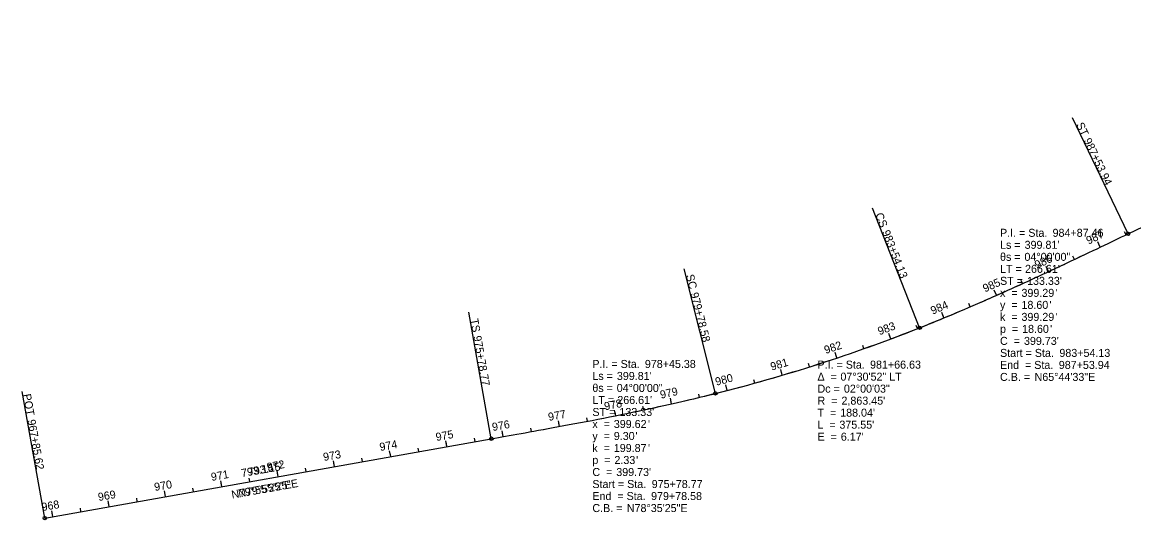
# Model space of a CAD drawing. Extents: x 2192013 to 2197996, y 660216 to 661764.
# Drawn here: x 2192013 to 2193957, y 660216 to 661086 of the extents above; entities that cross this region are included whole.
import ezdxf

# ---------------------------------------------------------------- set-up
doc = ezdxf.new("R2010")
doc.units = 0
for name, color, linetype in [('Default', 7, 'Continuous'), ('GE_X_Alignment', 7, 'Continuous'), ('GE_X_Alignment_1000_Curve_Data', 7, 'Continuous'), ('GE_X_Alignment_1000_Stations', 7, 'Continuous'), ('GE_X_Alignment_100_Curve_Data', 7, 'Continuous'), ('GE_X_Alignment_100_Stations', 7, 'Continuous'), ('GE_X_Alignment_500_Curve_Data', 7, 'Continuous'), ('GE_X_Alignment_500_Stations', 7, 'Continuous'), ('SC_Scratch1', 7, 'Continuous')]:
    doc.layers.add(name, color=color, linetype=linetype)

msp = doc.modelspace()

# ---------------------------------------------------------------- linework, layer by layer
at = {"layer": 'Default'}
for centre in [(2193946.9, 660715.8), (2193946.9, 660715.8), (2193946.9, 660715.8), (2193898.2, 660692.5), (2193807.8, 660649.8), (2193764.7, 660633.7), (2193764.7, 660633.7), (2193764.7, 660633.7), (2193716.8, 660608.3), (2193716.8, 660608.3), (2193625, 660568.8), (2193582.4, 660551.6), (2193582.4, 660551.6), (2193582.4, 660551.6), (2193531.9, 660532.1), (2193403.8, 660494.1), (2193403.8, 660494.1), (2193403.8, 660494.1), (2193437.7, 660498.8), (2193342.3, 660468.7), (2193246, 660441.9), (2193246, 660441.9), (2193246, 660441.9), (2193225.2, 660436.7), (2193225.2, 660436.7), (2193225.2, 660436.7), (2193148.7, 660418.5), (2193029.3, 660397.1), (2193029.3, 660397.1), (2193029.3, 660397.1), (2193050.9, 660397.8), (2192952.7, 660379.1), (2192755.8, 660343.8), (2192755.8, 660343.8), (2192833.4, 660357.6), (2192833.4, 660357.6), (2192833.4, 660357.6), (2192854.3, 660361.3), (2192657.4, 660326.3), (2192558.9, 660308.8), (2192442.9, 660288.2), (2192442.9, 660288.2), (2192442.9, 660288.2), (2192442.9, 660288.2), (2192442.9, 660288.2), (2192442.9, 660288.2), (2192460.4, 660291.3), (2192362, 660273.8), (2192263.5, 660256.3), (2192263.5, 660256.3), (2192263.5, 660256.3), (2192165.1, 660238.8), (2192052.5, 660218.8), (2192052.5, 660218.8), (2192052.5, 660218.8), (2192066.6, 660221.3)]:
    msp.add_circle(centre, 0.0000833, dxfattribs=at)
at = {"layer": 'GE_X_Alignment'}
for p, q in [((2193946.9, 660715.8), (2194719.5, 661085.8)), ((2193946.9, 660715.8), (2194719.5, 661085.8)), ((2192052.5, 660218.8), (2192833.4, 660357.6)), ((2192052.5, 660218.8), (2192833.4, 660357.6))]:
    msp.add_line(p, q, dxfattribs=at)
for centre, radius, start, end in [((2192528.4, 663215.4), 2864.8, 284.0696, 291.5975), ((2192528.8, 663214.1), 2863.5, 284.0763, 291.5908), ((2192528.8, 663214.1), 2863.5, 284.0763, 291.5908), ((2192528.8, 663214.1), 2863.5, 284.0763, 291.5908)]:
    msp.add_arc(centre, radius, start, end, dxfattribs=at)
for points in [[(2193582.4, 660551.6), (2193597.9, 660557.7), (2193628.8, 660570.3), (2193690.2, 660596.3), (2193766.2, 660630.3), (2193841.6, 660665.6), (2193901.8, 660694.2), (2193931.9, 660708.6), (2193946.9, 660715.8)], [(2193582.4, 660551.6), (2193597.9, 660557.7), (2193628.8, 660570.3), (2193690.2, 660596.3), (2193766.2, 660630.3), (2193841.6, 660665.6), (2193901.8, 660694.2), (2193931.9, 660708.6), (2193946.9, 660715.8)], [(2193582.4, 660551.6), (2193597.9, 660557.7), (2193628.8, 660570.3), (2193690.2, 660596.3), (2193766.2, 660630.3), (2193841.6, 660665.6), (2193901.8, 660694.2), (2193931.9, 660708.6), (2193946.9, 660715.8)], [(2193582.8, 660551.7), (2193598.3, 660557.9), (2193629.1, 660570.4), (2193690.4, 660596.4), (2193766.4, 660630.3), (2193841.7, 660665.6), (2193901.8, 660694.2), (2193931.8, 660708.6), (2193946.8, 660715.8)], [(2192833.4, 660357.6), (2192849.8, 660360.5), (2192882.6, 660366.3), (2192948.2, 660378.1), (2193030, 660393.4), (2193111.6, 660410.1), (2193176.7, 660424.8), (2193209, 660432.6), (2193225.2, 660436.7)], [(2192833.4, 660357.6), (2192849.8, 660360.5), (2192882.6, 660366.3), (2192948.2, 660378.1), (2193030, 660393.4), (2193111.6, 660410.1), (2193176.7, 660424.8), (2193209, 660432.6), (2193225.2, 660436.7)], [(2192833.4, 660357.6), (2192849.8, 660360.5), (2192882.6, 660366.3), (2192948.2, 660378.1), (2193030, 660393.4), (2193111.6, 660410.1), (2193176.7, 660424.8), (2193209, 660432.6), (2193225.2, 660436.7)], [(2192833.4, 660357.6), (2192849.8, 660360.5), (2192882.6, 660366.3), (2192948.1, 660378.1), (2193029.9, 660393.4), (2193111.4, 660410.1), (2193176.3, 660424.7), (2193208.6, 660432.5), (2193224.8, 660436.6)]]:
    msp.add_open_spline(points, degree=3, dxfattribs=at)
at = {"layer": 'GE_X_Alignment_1000_Stations'}
for p, q in [((2193946.9, 660715.8), (2193849.7, 660918.7)), ((2193582.4, 660551.6), (2193499.7, 660760.8)), ((2193225.2, 660436.7), (2193170.5, 660654.9)), ((2193716.8, 660608.3), (2193714.4, 660613.8)), ((2192833.4, 660357.6), (2192794, 660579.1)), ((2193246, 660441.9), (2193243.4, 660451.6)), ((2192052.5, 660218.8), (2192013.1, 660440.3)), ((2192755.8, 660343.8), (2192754.8, 660349.7)), ((2192263.5, 660256.3), (2192261.8, 660266.2))]:
    msp.add_line(p, q, dxfattribs=at)
for centre in [(2193946.9, 660715.8), (2193582.4, 660551.6), (2193225.2, 660436.7), (2192833.4, 660357.6), (2192052.5, 660218.8)]:
    msp.add_circle(centre, 3, dxfattribs=at)
at = {"layer": 'GE_X_Alignment_100_Stations'}
for p, q in [((2193946.9, 660715.8), (2193849.7, 660918.7)), ((2193582.4, 660551.6), (2193499.7, 660760.8)), ((2193943.3, 660714.1), (2193940.7, 660719.5)), ((2193898.2, 660692.5), (2193893.9, 660701.6)), ((2193853.1, 660671.1), (2193850.5, 660676.5)), ((2193225.2, 660436.7), (2193170.5, 660654.9)), ((2193807.8, 660649.8), (2193803.6, 660658.9)), ((2193716.8, 660608.3), (2193712.8, 660617.4)), ((2193762.4, 660628.8), (2193759.9, 660634.3)), ((2192833.4, 660357.6), (2192794, 660579.1)), ((2193625, 660568.8), (2193621.1, 660578)), ((2193671, 660588.2), (2193668.7, 660593.7)), ((2193531.9, 660532.1), (2193528.4, 660541.5)), ((2193578.6, 660550.1), (2193576.4, 660555.7)), ((2193484.9, 660515), (2193482.9, 660520.7)), ((2193437.7, 660498.8), (2193434.5, 660508.2)), ((2193390.1, 660483.3), (2193388.3, 660489)), ((2193294.2, 660454.9), (2193292.6, 660460.7)), ((2193342.3, 660468.7), (2193339.5, 660478.3)), ((2193246, 660441.9), (2193243.4, 660451.6)), ((2192052.5, 660218.8), (2192013.1, 660440.3)), ((2193148.7, 660418.5), (2193146.5, 660428.3)), ((2193197.4, 660429.8), (2193196, 660435.7)), ((2193050.9, 660397.8), (2193048.9, 660407.6)), ((2193099.9, 660407.9), (2193098.6, 660413.8)), ((2192952.7, 660379.1), (2192950.9, 660388.9)), ((2193001.8, 660388.3), (2193000.7, 660394.2)), ((2192854.3, 660361.3), (2192852.5, 660371.1)), ((2192903.5, 660370.1), (2192902.4, 660376)), ((2192755.8, 660343.8), (2192754.1, 660353.7)), ((2192805, 660352.6), (2192804, 660358.5)), ((2192657.4, 660326.3), (2192655.6, 660336.2)), ((2192706.6, 660335.1), (2192705.5, 660341)), ((2192509.7, 660300.1), (2192508.6, 660306)), ((2192558.9, 660308.8), (2192557.2, 660318.7)), ((2192608.1, 660317.6), (2192607.1, 660323.5)), ((2192411.2, 660282.6), (2192410.2, 660288.5)), ((2192460.4, 660291.3), (2192458.7, 660301.2)), ((2192263.5, 660256.3), (2192261.8, 660266.2)), ((2192312.8, 660265.1), (2192311.7, 660271)), ((2192362, 660273.8), (2192360.2, 660283.7)), ((2192165.1, 660238.8), (2192163.3, 660248.7)), ((2192214.3, 660247.6), (2192213.3, 660253.5)), ((2192066.6, 660221.3), (2192064.9, 660231.2)), ((2192115.8, 660230.1), (2192114.8, 660236))]:
    msp.add_line(p, q, dxfattribs=at)
for centre in [(2193946.9, 660715.8), (2193582.4, 660551.6), (2193225.2, 660436.7), (2192833.4, 660357.6), (2192052.5, 660218.8)]:
    msp.add_circle(centre, 3, dxfattribs=at)
at = {"layer": 'GE_X_Alignment_500_Stations'}
for p, q in [((2193946.9, 660715.8), (2193849.7, 660918.7)), ((2193582.4, 660551.6), (2193499.7, 660760.8)), ((2193898.2, 660692.5), (2193895.6, 660697.9)), ((2193225.2, 660436.7), (2193170.5, 660654.9)), ((2193807.8, 660649.8), (2193805.3, 660655.2)), ((2193716.8, 660608.3), (2193712.8, 660617.4)), ((2192833.4, 660357.6), (2192794, 660579.1)), ((2193625, 660568.8), (2193622.7, 660574.3)), ((2193531.9, 660532.1), (2193529.8, 660537.8)), ((2193437.7, 660498.8), (2193435.8, 660504.4)), ((2193342.3, 660468.7), (2193340.6, 660474.4)), ((2193246, 660441.9), (2193243.4, 660451.6)), ((2192052.5, 660218.8), (2192013.1, 660440.3)), ((2193148.7, 660418.5), (2193147.4, 660424.4)), ((2193050.9, 660397.8), (2193049.7, 660403.7)), ((2192952.7, 660379.1), (2192951.6, 660385)), ((2192854.3, 660361.3), (2192853.2, 660367.2)), ((2192755.8, 660343.8), (2192754.1, 660353.7)), ((2192657.4, 660326.3), (2192656.3, 660332.2)), ((2192558.9, 660308.8), (2192557.9, 660314.7)), ((2192460.4, 660291.3), (2192459.4, 660297.2)), ((2192263.5, 660256.3), (2192261.8, 660266.2)), ((2192362, 660273.8), (2192360.9, 660279.7)), ((2192066.6, 660221.3), (2192065.6, 660227.2)), ((2192165.1, 660238.8), (2192164, 660244.7))]:
    msp.add_line(p, q, dxfattribs=at)
for centre in [(2193946.9, 660715.8), (2193582.4, 660551.6), (2193225.2, 660436.7), (2192833.4, 660357.6), (2192052.5, 660218.8)]:
    msp.add_circle(centre, 3, dxfattribs=at)
at = {"layer": 'SC_Scratch1'}
for q in [(2194719.5, 661085.8), (2193947, 660715.9)]:
    msp.add_line((2193946.9, 660715.8), q, dxfattribs=at)

# ---------------------------------------------------------------- texts
at = {"layer": 'GE_X_Alignment_1000_Curve_Data'}
for s, p in [('P.I. = Sta. ', (2193723, 660710.6)), ('984+87.46', (2193814.9, 660710.6)), ('Ls = ', (2193723, 660689.6)), ("399.81'", (2193766, 660689.6)), ('θs = ', (2193723, 660668.6)), ('04°00\'00"', (2193765.7, 660668.6)), ('LT = ', (2193723, 660647.6)), ("266.61'", (2193766.7, 660647.6)), ('ST = ', (2193723, 660626.6)), ("133.33'", (2193770.3, 660626.6)), ('x  = ', (2193723, 660605.6)), ('399.29', (2193760.5, 660605.6)), ("'", (2193820.3, 660605.6)), ('18.60', (2193760.5, 660584.6)), ("'", (2193809.5, 660584.6)), ('y  = ', (2193723, 660584.6)), ('k  = ', (2193723, 660563.6)), ('399.29', (2193760.5, 660563.6)), ("'", (2193820.3, 660563.6)), ('p  = ', (2193723, 660542.6)), ('18.60', (2193761.6, 660542.6)), ("'", (2193810.6, 660542.6)), ('C  = ', (2193723, 660521.6)), ("399.73'", (2193764.9, 660521.6)), ('Start = Sta. ', (2193723, 660500.6)), ('983+54.13', (2193826.8, 660500.6)), ('P.I. = Sta. ', (2193010.1, 660481.3)), ('978+45.38', (2193101.9, 660481.3)), ('P.I. = Sta. ', (2193403.8, 660480.1)), ('981+66.63', (2193495.7, 660480.1)), ('End  = Sta. ', (2193723, 660479.6)), ('987+53.94', (2193825.8, 660479.6)), ('Ls = ', (2193010.1, 660460.3)), ("399.81'", (2193053, 660460.3)), ('Δ  = ', (2193403.8, 660459.1)), ('07°30\'52" LT', (2193443.9, 660459.1)), ('C.B. = ', (2193723, 660458.6)), ('N65°44\'33"E', (2193783.4, 660458.6)), ('θs = ', (2193010.1, 660439.3)), ('04°00\'00"', (2193052.7, 660439.3)), ('Dc = ', (2193403.8, 660438.1)), ('02°00\'03"', (2193450, 660438.1)), ('LT = ', (2193010.1, 660418.3)), ("266.61'", (2193053.7, 660418.3)), ('R  = ', (2193403.8, 660417.1)), ("2,863.45'", (2193445.7, 660417.1)), ('ST = ', (2193010.1, 660397.3)), ("133.33'", (2193057.4, 660397.3)), ('T  = ', (2193403.8, 660396.1)), ("188.04'", (2193443.5, 660396.1)), ('x  = ', (2193010.1, 660376.3)), ('399.62', (2193047.6, 660376.3)), ("'", (2193107.4, 660376.3)), ('L  = ', (2193403.8, 660375.1)), ("375.55'", (2193442.1, 660375.1)), ('y  = ', (2193010.1, 660355.3)), ('9.30', (2193047.6, 660355.3)), ("'", (2193085.6, 660355.3)), ('E  = ', (2193403.8, 660354.1)), ("6.17'", (2193444.6, 660354.1)), ('k  = ', (2193010.1, 660334.3)), ('199.87', (2193047.6, 660334.3)), ("'", (2193107.4, 660334.3)), ('p  = ', (2193010.1, 660313.3)), ('2.33', (2193048.7, 660313.3)), ("'", (2193086.7, 660313.3)), ('C  = ', (2193010.1, 660292.3)), ("399.73'", (2193051.9, 660292.3)), ('Start = Sta. ', (2193010.1, 660271.3)), ('975+78.77', (2193113.9, 660271.3)), ('End  = Sta. ', (2193010.1, 660250.3)), ('979+78.58', (2193112.8, 660250.3)), ('C.B. = ', (2193010.1, 660229.3)), ('N78°35\'25"E', (2193070.4, 660229.3))]:
    msp.add_text(s, height=14, dxfattribs=at).set_placement(p)
at = {"layer": 'GE_X_Alignment_1000_Stations'}
for s, rotation, p in [('ST', 295.5908, (2193855.7, 660906.7)), ('987+53.94', 295.5908, (2193868.8, 660879.3)), ('CS', 291.5908, (2193504.4, 660749.5)), ('983+54.13', 291.5908, (2193516.4, 660719.2)), ('SC', 284.0763, (2193173.7, 660643.2)), ('979+78.58', 284.0763, (2193181.6, 660611.6)), ('TS', 280.0763, (2192796.5, 660566.4)), ('975+78.77', 280.0763, (2192801.8, 660536.5)), ('980', 14.5048, (2193226.9, 660450.2)), ('POT', 280.0763, (2192014.3, 660434.8)), ('967+85.62', 280.0763, (2192022.3, 660389.9)), ("793.15'", 10.0763, (2192409.2, 660292.4)), ('N79°55\'25"E', 10.0763, (2192392.1, 660254.8)), ('970', 10.0763, (2192245.2, 660266))]:
    msp.add_text(s, height=14, rotation=rotation, dxfattribs=at).set_placement(p)
at = {"layer": 'GE_X_Alignment_100_Curve_Data'}
for s, p in [('P.I. = Sta. ', (2193723, 660710.6)), ('984+87.46', (2193814.9, 660710.6)), ('Ls = ', (2193723, 660689.6)), ("399.81'", (2193766, 660689.6)), ('θs = ', (2193723, 660668.6)), ('04°00\'00"', (2193765.7, 660668.6)), ('LT = ', (2193723, 660647.6)), ("266.61'", (2193766.7, 660647.6)), ('ST = ', (2193723, 660626.6)), ("133.33'", (2193770.3, 660626.6)), ('x  = ', (2193723, 660605.6)), ('399.29', (2193760.5, 660605.6)), ("'", (2193820.3, 660605.6)), ('18.60', (2193760.5, 660584.6)), ("'", (2193809.5, 660584.6)), ('y  = ', (2193723, 660584.6)), ('k  = ', (2193723, 660563.6)), ('399.29', (2193760.5, 660563.6)), ("'", (2193820.3, 660563.6)), ('p  = ', (2193723, 660542.6)), ('18.60', (2193761.6, 660542.6)), ("'", (2193810.6, 660542.6)), ('C  = ', (2193723, 660521.6)), ("399.73'", (2193764.9, 660521.6)), ('Start = Sta. ', (2193723, 660500.6)), ('983+54.13', (2193826.8, 660500.6)), ('P.I. = Sta. ', (2193010.1, 660481.3)), ('978+45.38', (2193101.9, 660481.3)), ('P.I. = Sta. ', (2193403.8, 660480.1)), ('981+66.63', (2193495.7, 660480.1)), ('End  = Sta. ', (2193723, 660479.6)), ('987+53.94', (2193825.8, 660479.6)), ('Ls = ', (2193010.1, 660460.3)), ("399.81'", (2193053, 660460.3)), ('Δ  = ', (2193403.8, 660459.1)), ('07°30\'52" LT', (2193443.9, 660459.1)), ('C.B. = ', (2193723, 660458.6)), ('N65°44\'33"E', (2193783.4, 660458.6)), ('θs = ', (2193010.1, 660439.3)), ('04°00\'00"', (2193052.7, 660439.3)), ('Dc = ', (2193403.8, 660438.1)), ('02°00\'03"', (2193450, 660438.1)), ('LT = ', (2193010.1, 660418.3)), ("266.61'", (2193053.7, 660418.3)), ('R  = ', (2193403.8, 660417.1)), ("2,863.45'", (2193445.7, 660417.1)), ('ST = ', (2193010.1, 660397.3)), ("133.33'", (2193057.4, 660397.3)), ('T  = ', (2193403.8, 660396.1)), ("188.04'", (2193443.5, 660396.1)), ('x  = ', (2193010.1, 660376.3)), ('399.62', (2193047.6, 660376.3)), ("'", (2193107.4, 660376.3)), ('L  = ', (2193403.8, 660375.1)), ("375.55'", (2193442.1, 660375.1)), ('y  = ', (2193010.1, 660355.3)), ('9.30', (2193047.6, 660355.3)), ("'", (2193085.6, 660355.3)), ('E  = ', (2193403.8, 660354.1)), ("6.17'", (2193444.6, 660354.1)), ('k  = ', (2193010.1, 660334.3)), ('199.87', (2193047.6, 660334.3)), ("'", (2193107.4, 660334.3)), ('p  = ', (2193010.1, 660313.3)), ('2.33', (2193048.7, 660313.3)), ("'", (2193086.7, 660313.3)), ('C  = ', (2193010.1, 660292.3)), ("399.73'", (2193051.9, 660292.3)), ('Start = Sta. ', (2193010.1, 660271.3)), ('975+78.77', (2193113.9, 660271.3)), ('End  = Sta. ', (2193010.1, 660250.3)), ('979+78.58', (2193112.8, 660250.3)), ('C.B. = ', (2193010.1, 660229.3)), ('N78°35\'25"E', (2193070.4, 660229.3))]:
    msp.add_text(s, height=14, dxfattribs=at).set_placement(p)
at = {"layer": 'GE_X_Alignment_100_Stations'}
for s, rotation, p in [('ST', 295.5908, (2193855.7, 660906.7)), ('987+53.94', 295.5908, (2193868.8, 660879.3)), ('CS', 291.5908, (2193504.4, 660749.5)), ('983+54.13', 291.5908, (2193516.4, 660719.2)), ('987', 25.5179, (2193877.7, 660696.8)), ('986', 24.9977, (2193787.5, 660654.4)), ('SC', 284.0763, (2193173.7, 660643.2)), ('985', 23.9771, (2193696.6, 660613.2)), ('979+78.58', 284.0763, (2193181.6, 660611.6)), ('984', 22.4559, (2193605.1, 660574.4)), ('TS', 280.0763, (2192796.5, 660566.4)), ('983', 20.5076, (2193512.2, 660538.4)), ('975+78.77', 280.0763, (2192801.8, 660536.5)), ('982', 18.5067, (2193418.1, 660505.6)), ('981', 16.5058, (2193323.8, 660476.5)), ('980', 14.5048, (2193226.9, 660450.2)), ('979', 12.6584, (2193130.1, 660427.4)), ('POT', 280.0763, (2192014.3, 660434.8)), ('978', 11.301, (2193032.3, 660407.1)), ('977', 10.4441, (2192934, 660388.6)), ('967+85.62', 280.0763, (2192022.3, 660389.9)), ('976', 10.0876, (2192835.9, 660371)), ('975', 10.0763, (2192737.4, 660353.5)), ('974', 10.0763, (2192639.2, 660336)), ('973', 10.0763, (2192540.6, 660318.5)), ("793.15'", 10.0763, (2192397.3, 660290.3)), ('972', 10.0763, (2192442.1, 660301)), ('971', 10.0763, (2192344.4, 660283.6)), ('969', 10.0763, (2192146.8, 660248.5)), ('970', 10.0763, (2192245.2, 660266)), ('N79°55\'25"E', 10.0763, (2192380.2, 660252.7)), ('968', 10.0763, (2192048.2, 660231))]:
    msp.add_text(s, height=14, rotation=rotation, dxfattribs=at).set_placement(p)
at = {"layer": 'GE_X_Alignment_500_Curve_Data'}
for s, p in [('P.I. = Sta. ', (2193723, 660710.6)), ('984+87.46', (2193814.9, 660710.6)), ('Ls = ', (2193723, 660689.6)), ("399.81'", (2193766, 660689.6)), ('θs = ', (2193723, 660668.6)), ('04°00\'00"', (2193765.7, 660668.6)), ('LT = ', (2193723, 660647.6)), ("266.61'", (2193766.7, 660647.6)), ('ST = ', (2193723, 660626.6)), ("133.33'", (2193770.3, 660626.6)), ('x  = ', (2193723, 660605.6)), ('399.29', (2193760.5, 660605.6)), ("'", (2193820.3, 660605.6)), ('18.60', (2193760.5, 660584.6)), ("'", (2193809.5, 660584.6)), ('y  = ', (2193723, 660584.6)), ('k  = ', (2193723, 660563.6)), ('399.29', (2193760.5, 660563.6)), ("'", (2193820.3, 660563.6)), ('p  = ', (2193723, 660542.6)), ('18.60', (2193761.6, 660542.6)), ("'", (2193810.6, 660542.6)), ('C  = ', (2193723, 660521.6)), ("399.73'", (2193764.9, 660521.6)), ('Start = Sta. ', (2193723, 660500.6)), ('983+54.13', (2193826.8, 660500.6)), ('P.I. = Sta. ', (2193010.1, 660481.3)), ('978+45.38', (2193101.9, 660481.3)), ('P.I. = Sta. ', (2193403.8, 660480.1)), ('981+66.63', (2193495.7, 660480.1)), ('End  = Sta. ', (2193723, 660479.6)), ('987+53.94', (2193825.8, 660479.6)), ('Ls = ', (2193010.1, 660460.3)), ("399.81'", (2193053, 660460.3)), ('Δ  = ', (2193403.8, 660459.1)), ('07°30\'52" LT', (2193443.9, 660459.1)), ('C.B. = ', (2193723, 660458.6)), ('N65°44\'33"E', (2193783.4, 660458.6)), ('θs = ', (2193010.1, 660439.3)), ('04°00\'00"', (2193052.7, 660439.3)), ('Dc = ', (2193403.8, 660438.1)), ('02°00\'03"', (2193450, 660438.1)), ('LT = ', (2193010.1, 660418.3)), ("266.61'", (2193053.7, 660418.3)), ('R  = ', (2193403.8, 660417.1)), ("2,863.45'", (2193445.7, 660417.1)), ('ST = ', (2193010.1, 660397.3)), ("133.33'", (2193057.4, 660397.3)), ('T  = ', (2193403.8, 660396.1)), ("188.04'", (2193443.5, 660396.1)), ('x  = ', (2193010.1, 660376.3)), ('399.62', (2193047.6, 660376.3)), ("'", (2193107.4, 660376.3)), ('L  = ', (2193403.8, 660375.1)), ("375.55'", (2193442.1, 660375.1)), ('y  = ', (2193010.1, 660355.3)), ('9.30', (2193047.6, 660355.3)), ("'", (2193085.6, 660355.3)), ('E  = ', (2193403.8, 660354.1)), ("6.17'", (2193444.6, 660354.1)), ('k  = ', (2193010.1, 660334.3)), ('199.87', (2193047.6, 660334.3)), ("'", (2193107.4, 660334.3)), ('p  = ', (2193010.1, 660313.3)), ('2.33', (2193048.7, 660313.3)), ("'", (2193086.7, 660313.3)), ('C  = ', (2193010.1, 660292.3)), ("399.73'", (2193051.9, 660292.3)), ('Start = Sta. ', (2193010.1, 660271.3)), ('975+78.77', (2193113.9, 660271.3)), ('End  = Sta. ', (2193010.1, 660250.3)), ('979+78.58', (2193112.8, 660250.3)), ('C.B. = ', (2193010.1, 660229.3)), ('N78°35\'25"E', (2193070.4, 660229.3))]:
    msp.add_text(s, height=14, dxfattribs=at).set_placement(p)
at = {"layer": 'GE_X_Alignment_500_Stations'}
for s, rotation, p in [('ST', 295.5908, (2193855.7, 660906.7)), ('987+53.94', 295.5908, (2193868.8, 660879.3)), ('CS', 291.5908, (2193504.4, 660749.5)), ('983+54.13', 291.5908, (2193516.4, 660719.2)), ('SC', 284.0763, (2193173.7, 660643.2)), ('985', 23.9771, (2193696.6, 660613.2)), ('979+78.58', 284.0763, (2193181.6, 660611.6)), ('TS', 280.0763, (2192796.5, 660566.4)), ('975+78.77', 280.0763, (2192801.8, 660536.5)), ('980', 14.5048, (2193226.9, 660450.2)), ('POT', 280.0763, (2192014.3, 660434.8)), ('967+85.62', 280.0763, (2192022.3, 660389.9)), ('975', 10.0763, (2192737.4, 660353.5)), ("793.15'", 10.0763, (2192409.2, 660292.4)), ('N79°55\'25"E', 10.0763, (2192392.1, 660254.8)), ('970', 10.0763, (2192245.2, 660266))]:
    msp.add_text(s, height=14, rotation=rotation, dxfattribs=at).set_placement(p)

doc.saveas('drawing.dxf')
